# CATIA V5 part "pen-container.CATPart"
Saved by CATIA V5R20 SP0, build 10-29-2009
Part number: Part1
Material "Cedar": density 750 kg/m3, Young's modulus 1.5e+10 Pa
Bounding box of the stored display mesh (mm): x -55.827 to 55.827, y -56 to 56, z -2.361 to 115
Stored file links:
  D:\工程制图\pen-container.CATPart
  D:\CATIA v5\win_b64\startup\materials\Catalog.CATMaterial
  D:\CATIA v5\win_b64\startup\materials\alpin_fir.jpg
  D:\CATIA v5\win_b64\startup\materials\cedar.jpg
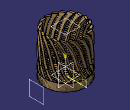
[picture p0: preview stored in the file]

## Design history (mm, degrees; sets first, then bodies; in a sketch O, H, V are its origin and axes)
Body1 (main body), material "Cedar"
  Cylinder1: Direction (0, 0, 1), Length1 120, Length2 0, Radius 50, Center {point type Coord, X 0, Y 0, Z 0}
  Plane1: type Offset, RefPlane yz-plane, Offset 80
  Sketch1 on Plane1, origin (80, 0, 0), H (0, 1, 0), V (0, 0, 1)
    spline S1 through (37.0005, 0) (0, 40) (-12.676, 83.9775) (-33.5924, 120)
    reference projected line E1 (50, 120) -> (-50, 120) from edge of Cylinder1
    reference projected line E2 through (0, 0) direction (0, 1) from axis of face of Cylinder1
    reference projected line E3 through (0, 0) direction (0, 1) from axis of face of Cylinder1
    reference projected line E4 (-50, 0) -> (50, 0) from edge of Cylinder1
    reference projected line E5 (-50, 0) -> (50, 0) from edge of Cylinder1
    reference projected line E6 through (0, 0) direction (0, 1) from axis of face of Cylinder1
    point P1 (37.0005, 0)
    point P2 (0, 40)
    point P3 (-33.5924, 120)
    point P4 (-12.676, 83.9775)
    distance P4 E2 = 12.676
    distance P3 E3 = 33.5924
    distance P2 E4 = 40
    distance P4 E5 = 83.9775
    distance P1 E6 = 37.0005
    coincidence: P1 H, P2 V, P3 E1
  Project1: ToProject Sketch1, Support Cylinder1, Direction (1, 0, 0)
  Plane2: type Normal, Curve Project1, RefPoint vertex of Project1
  Sketch2 on Plane2, origin (0, 0, 0), H (-0.6726, -0.74, 0), V (-0.2433, 0.2211, 0.9444)
    point P1 (-50, 0)
    line L1 (-45, 2.5) -> (-45, -2.5)
    line L2 (-45, -2.5) -> (-55, -2.5)
    line L3 (-55, -2.5) -> (-55, 2.5)
    line L4 (-55, 2.5) -> (-45, 2.5)
    reference projected point E1 (-50, 0) from vertex of Project1
    length L2 = 10
    length L3 = 5
    vertical: L1 V, L3 V
    horizontal: L2 H, L4 H
    equidistance: L1 L3 P1, L2 L4 P1
    coincidence: P1 E1
  Rib1: profile Sketch2, centre curve Project1
  CircPattern1: of the body so far, instances 20, angular step 18.9474, axis from Z axis
  Helix1: Direction Z axis, RefPoint {point type Coord, X 50, Y 0, Z 0}, Pitch 5, Height 110, TaperAngle 0
  Sweep1: type Circle, Guide Helix1, Radius 1
  CloseSurface1: CloseElement Sweep1
  Sketch3 on yz-plane, origin (0, 0, 0), H (0, 1, 0), V (0, 0, 1)
    point P1 (0, -1)
    line L1 (0, -1) -> (56, -1)
    line L2 (56, -1) -> (56, 19)
    distance H L1 = 1
    length L1 = 56
    length L2 = 20
    coincidence: P1 V
    horizontal: L1 H
    vertical: L2 V
  Revol1: Element1 Sketch3, Angle1 360, Line Z axis
  ThickSurface1: Surface Revol1, TopOffset 1, BotOffset 0
  Plane3: type Offset, RefPlane xy-plane, Offset 115
  Split1: SplitPlane Plane3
